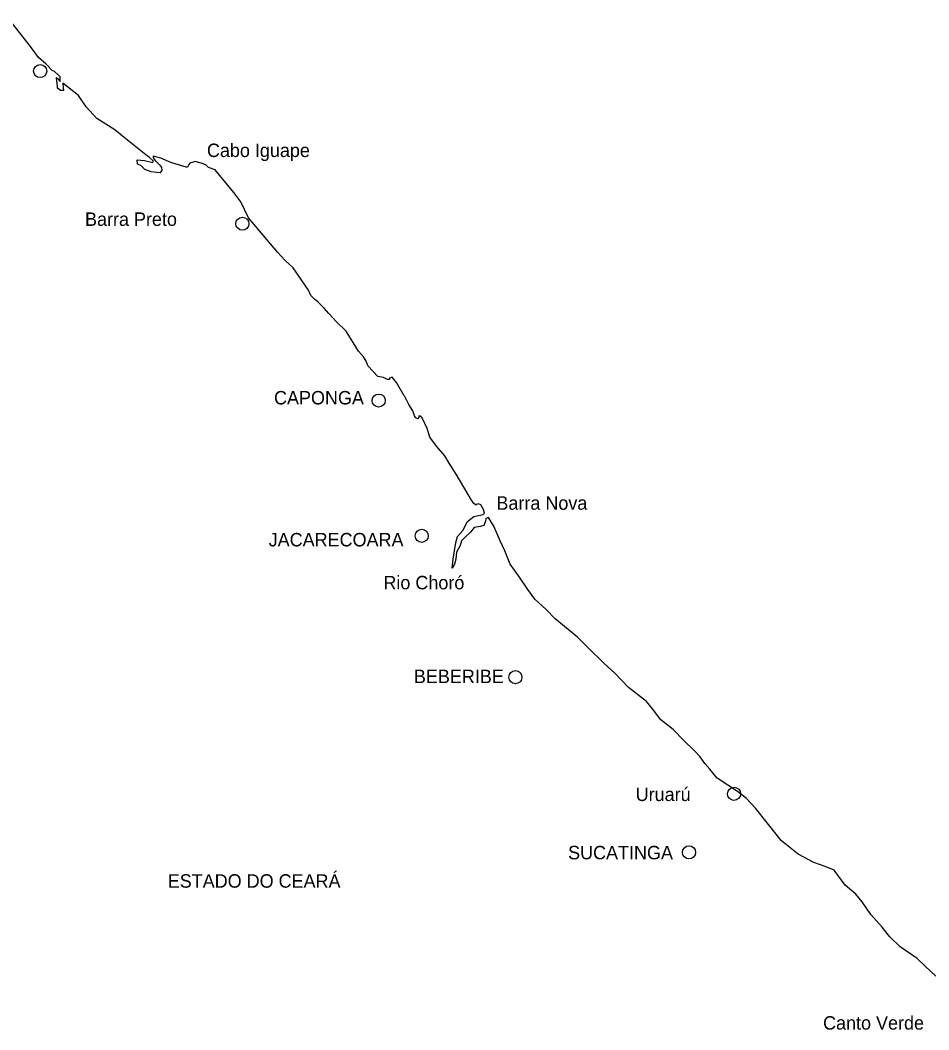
# Model space of a CAD drawing. Extents: x 662444 to 1640468, y 7452018 to 9606170.
# Drawn here: x 1238625 to 1284994, y 9517099 to 9568629 of the extents above; entities that cross this region are included whole.
import ezdxf

# ---------------------------------------------------------------- set-up
doc = ezdxf.new("R2010")
doc.units = 0
for name, color, linetype in [('Level 1', 7, 'Continuous'), ('Level 2', 7, 'Continuous'), ('Level 3', 7, 'Continuous')]:
    doc.layers.add(name, color=color, linetype=linetype)

msp = doc.modelspace()

# ---------------------------------------------------------------- linework, layer by layer
at = {"layer": 'Level 1'}
for points in [[(1241991, 9564199), (1241600, 9564785), (1240795, 9565423), (1240826, 9565196), (1240832, 9565035), (1240792, 9565035), (1240686, 9565036), (1240525, 9565151), (1240526, 9565264), (1240488, 9565515), (1240474, 9565710), (1240554, 9565628), (1240658, 9565506), (1240660, 9565741), (1240556, 9565838), (1240379, 9566002), (1240258, 9566068), (1239953, 9566386), (1239567, 9566722), (1239151, 9567292), (1238102, 9568629)], [(1260665, 9540666), (1260719, 9541119), (1260857, 9541968), (1260942, 9542283), (1261213, 9542589), (1261453, 9543048), (1261772, 9543304), (1262016, 9543342), (1262260, 9543405), (1262318, 9543469), (1262262, 9543655), (1262127, 9543900), (1262014, 9543949), (1261900, 9543910), (1261900, 9543870), (1261843, 9543903), (1261771, 9543968), (1261659, 9544139), (1261484, 9544416), (1260870, 9545459), (1260519, 9546021), (1260296, 9546388), (1259863, 9546893), (1259536, 9547350), (1259386, 9547789), (1259141, 9548334), (1259044, 9548423), (1258970, 9548433), (1258977, 9548335), (1258921, 9548280), (1258815, 9548337), (1258751, 9548443), (1258657, 9548686), (1258450, 9549021), (1258259, 9549428), (1258227, 9549452), (1257821, 9550136), (1257604, 9550413), (1257466, 9550358), (1257465, 9550285), (1257367, 9550286), (1257158, 9550393), (1256874, 9550437), (1256385, 9550975), (1256258, 9551260), (1256147, 9551455), (1255898, 9551733), (1255268, 9552759), (1254761, 9553225), (1254369, 9553658), (1254144, 9553935), (1253839, 9554230), (1253646, 9554386), (1253461, 9554573), (1253335, 9554858), (1253182, 9555078), (1252935, 9555437), (1252559, 9555982), (1252141, 9556358), (1251781, 9556775), (1250274, 9558545), (1249893, 9559351), (1249524, 9559840), (1248570, 9560990), (1248231, 9561114), (1248095, 9561253), (1247868, 9561329), (1247553, 9561413), (1247276, 9561334), (1247226, 9561269), (1247160, 9561133), (1247088, 9561134), (1246812, 9561208), (1246319, 9561359), (1245810, 9561581), (1245414, 9561683), (1245414, 9561658), (1245453, 9561553), (1245518, 9561464), (1245613, 9561365), (1245726, 9561243), (1245830, 9561113), (1245852, 9560974), (1245762, 9560837), (1245592, 9560847), (1245316, 9560882), (1244985, 9561015), (1244784, 9561210), (1244615, 9561285), (1244592, 9561503), (1244965, 9561476), (1245395, 9561359), (1245411, 9561455), (1245227, 9561627), (1245034, 9561751), (1243931, 9562635), (1243457, 9563036), (1242538, 9563619), (1241991, 9564199)], [(1285352, 9519831), (1284814, 9520339), (1284404, 9520732), (1283527, 9521333), (1282997, 9521848), (1282613, 9522338), (1282036, 9522984), (1281589, 9523637), (1281269, 9524021), (1280723, 9524488), (1280163, 9525239), (1279703, 9525430), (1279129, 9525630), (1278322, 9526060), (1277470, 9526749), (1276741, 9527663), (1276157, 9528407), (1275684, 9528906), (1275226, 9529258), (1274187, 9529949), (1273826, 9530398), (1273562, 9530692), (1273331, 9531035), (1273042, 9531345), (1272472, 9531885), (1271950, 9532434), (1271315, 9532917), (1270891, 9533481), (1270579, 9533857), (1269669, 9534562), (1268964, 9535305), (1268426, 9535797), (1267558, 9536639), (1267060, 9537138), (1265927, 9538073), (1265462, 9538555), (1264882, 9539071), (1264539, 9539576), (1264077, 9540253), (1263637, 9540865), (1263352, 9541539), (1263122, 9542052), (1262789, 9542808), (1262518, 9543240), (1262388, 9543193), (1262370, 9543063), (1262279, 9542846), (1262107, 9542791), (1261798, 9542729), (1261602, 9542495), (1261314, 9542232), (1261151, 9542063), (1261075, 9541812), (1260984, 9541627), (1260885, 9541474), (1260849, 9541118), (1260792, 9540859), (1260665, 9540666)]]:
    msp.add_lwpolyline(points, dxfattribs=at)
at = {"layer": 'Level 2'}
for centre, major_axis, ratio in [((1239642, 9566032), (335, -2), 0.999997), ((1249962, 9558241), (334, -2), 0.999997), ((1256919, 9549213), (335, -2), 0.999997), ((1259117, 9542309), (334, -3), 0.999997), ((1263899, 9535096), (334, -3), 0.999997), ((1275054, 9529146), (335, -3), 0.999998), ((1272757, 9526156), (335, -3), 0.999997)]:
    msp.add_ellipse(centre, major_axis=major_axis, ratio=ratio, dxfattribs=at)

# ---------------------------------------------------------------- texts
at = {"layer": 'Level 3'}
for s, height, p in [('Cabo Iguape', 686.18, (1248155, 9561644)), ('Barra Preto', 686.08, (1241933, 9558130)), ('CAPONGA', 686.1, (1251578, 9549017)), ('Barra Nova', 686.2, (1262927, 9543644)), ('JACARECOARA', 686.08, (1251305, 9541772)), ('Rio Choró', 686.1, (1257160, 9539581)), ('BEBERIBE', 686.1, (1258717, 9534794)), ('Uruarú', 686.2, (1270034, 9528774)), ('SUCATINGA', 686.1, (1266585, 9525801)), ('ESTADO DO CEARÁ', 685.89, (1246155, 9524353)), ('Canto Verde', 686.26, (1279597, 9517109))]:
    msp.add_text(s, height=height, dxfattribs=at).set_placement(p)

doc.saveas('drawing.dxf')
